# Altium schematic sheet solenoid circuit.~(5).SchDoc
size A; SheetNumber: 1; SheetTotal: 1
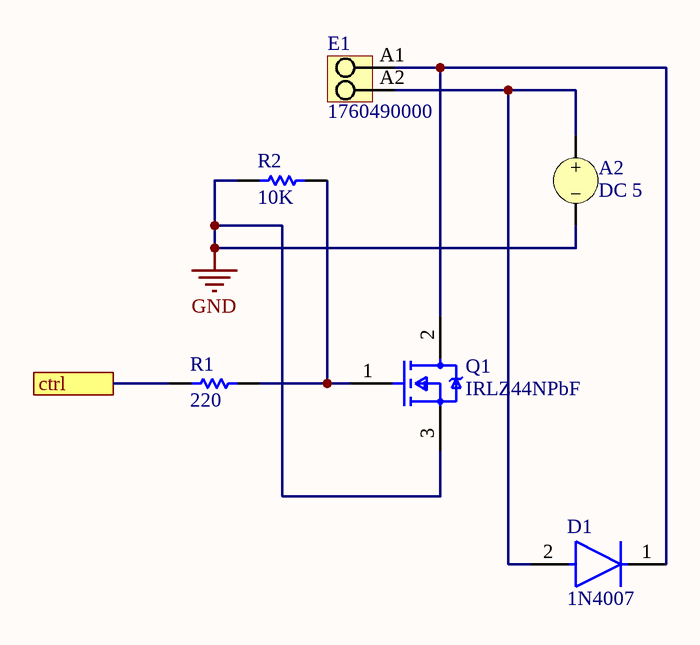
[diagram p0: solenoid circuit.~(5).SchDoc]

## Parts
A2  DC 5
D1  1N4007  [FP-1N4007-MFG]
E1  1760490000  [PM_5_08_90_02]
Q1  IRLZ44NPbF  [FP-PG-TO220-3-MFG]
R1  value 220  (hidden comment: Resistor)
R2  value 10K  (hidden comment: Resistor)

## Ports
ctrl

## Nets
GND: A2.2 Q1.3(S) R2.1
ctrl: R1.1 ; port ctrl
NetA2_1: A2.1 D1.2(A) E1.A2
NetD1_1: D1.1(C) E1.A1 Q1.2(D)
NetQ1_1: Q1.1(G) R1.2 R2.2

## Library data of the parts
A2 = VSRC: Voltage Source; Note: PCB Footprint - Not required; AC Magnitude: 1; AC Phase: 0; Value: 5
D1 = CMP-123542-000001-1: Rectifier diode 1000 V 1 A DO-41, ,; Manufacturer: Diotec; Max Surge Forward Current: 27A; Forward Current: 1A; Max Junction Temp: +175°C; Reverse Voltage: 1000V; Value: 15pF; Peak Reverse Current: 5uA
E1 = CMP-1559-01627-1: OMNIMATE Signal - series PM; Manufacturer: Weidmueller; Contact_surface: tinned; Pitch_mm: 5,08 mm; Solid_min_H05_07_V_U: 0,13 mm²; Wire_cross_section_AWG_min_UL_1059: AWG 26; Wire_cross_section_AWG_max_UL_1059: AWG 14; Rated_voltage_for_surge_voltage_class_pollution_degree_II_2: 600 V; Rated_current_use_group_B_UL_1059: 15 A; Mounting_onto_the_PCB: Solder connection; Solder_pin_length_mm: 3,5 mm; Side_termination_characteristic: closed side; Contact_material: Cu-Leg; Pitch_inch: 0,2 inch; No_of_poles: 2; UL_94_flammability_rating: V-0; Insulating_material: Wemid (PA); Rated_voltage_use_group_B_UL_1059: 300 V; Solid_max_H05_07_V_U: 2,5 mm²; Short_text_for_material: PM 5.08/02/90 3.5SN OR BX
Q1 = CMP-32901-000488-1: MOSFET N-CH 55V 47A TO220AB; Turn-On Delay Time: 11ns; Gate to Source Voltage (Vgs): 16V; Element Configuration: Single; Rds On Max: 22mR; Turn-Off Delay Time: 26ns; Max Power Dissipation: 110W; Threshold Voltage: 2V; Drain to Source Resistance: 35mR; Input Capacitance: 1.7nF
R1 R2 = Resistor: TC1: 0; SimulationGenericComponent: True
